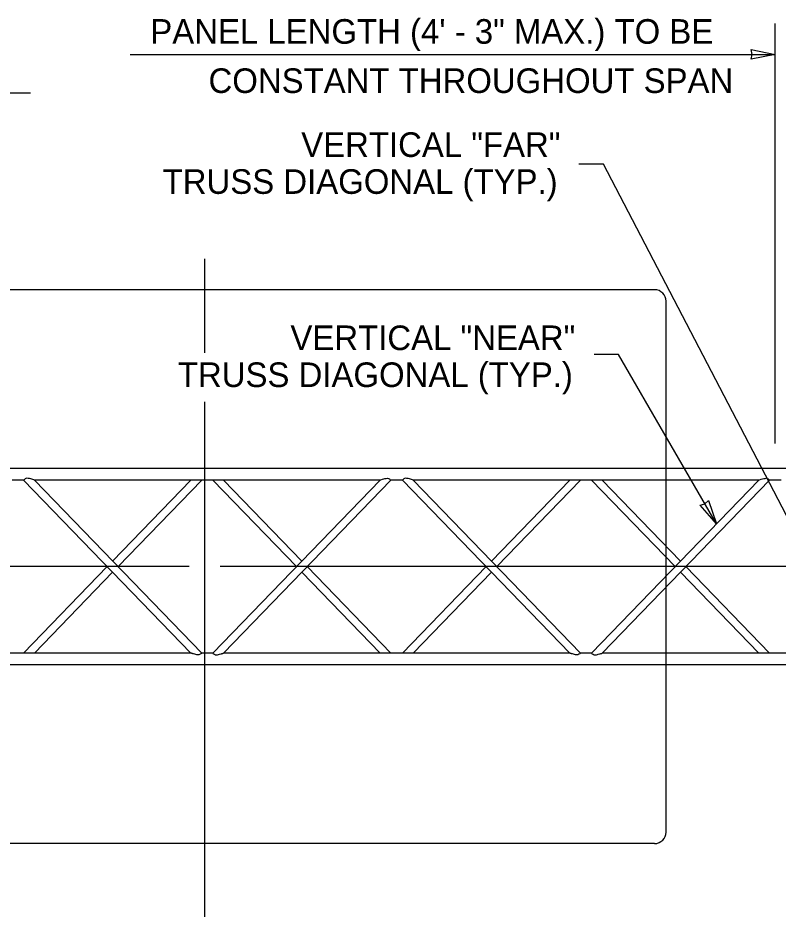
# Model space of a CAD drawing. Extents: x 99862 to 104211, y 98939 to 111076.
# Drawn here: x 101054 to 101548, y 101029 to 101608 of the extents above; entities that cross this region are included whole.
import ezdxf

# ---------------------------------------------------------------- set-up
doc = ezdxf.new("R2010")
doc.units = 0
for name, color, linetype in [('Level 15', 7, 'Continuous'), ('Level 20', 7, 'Continuous'), ('Level 6', 7, 'Continuous')]:
    doc.layers.add(name, color=color, linetype=linetype)

msp = doc.modelspace()

# ---------------------------------------------------------------- linework, layer by layer
at = {"layer": 'Level 15'}
for p, q in [((101546.37, 101331.16), (101546.37, 101604.16)), ((101126.95, 101584.16), (101546.37, 101584.16)), ((100920.81, 101559.16), (101062.26, 101559.16)), ((101434.65, 101512.85), (101418.65, 101512.85)), ((101582.66, 101228.49), (101434.65, 101512.85)), ((101175.37, 101451.16), (101175.37, 101390.1)), ((101444.54, 101389.08), (101428.54, 101389.08)), ((101508.13, 101278.95), (101444.55, 101389.08)), ((101175.37, 101358.32), (101175.37, 100843.55)), ((101165.37, 101251.16), (100695.37, 101251.16)), ((101773.38, 101251.16), (101185.37, 101251.16))]:
    msp.add_line(p, q, dxfattribs=at)
for points in [[(101546.37, 101584.16), (101530.64, 101581.08), (101531.37, 101584.16), (101530.64, 101587.25)], [(101508.13, 101278.95), (101497.6, 101291.02), (101500.63, 101291.93), (101502.94, 101294.11)]]:
    msp.add_lwpolyline(points, close=True, dxfattribs=at)
at = {"layer": 'Level 6'}
for p, q in [((101467.87, 101431.16), (100882.87, 101431.16)), ((101475.37, 101078.66), (101475.37, 101423.66)), ((101808.38, 101314.91), (100925.37, 101314.91)), ((101057.71, 101307.41), (101050.14, 101307.41)), ((101057.71, 101307.41), (101166.5, 101194.91)), ((101064.66, 101307.41), (101173.46, 101194.91)), ((101289.43, 101307.41), (101064.66, 101307.41)), ((101115.58, 101254.76), (101166.5, 101307.41)), ((101119.06, 101251.16), (101173.46, 101307.41)), ((101235.03, 101251.16), (101180.63, 101307.41)), ((101289.43, 101307.41), (101180.63, 101194.91)), ((101238.51, 101254.76), (101187.59, 101307.41)), ((101296.38, 101307.41), (101187.59, 101194.91)), ((101303.95, 101307.41), (101296.38, 101307.41)), ((101303.95, 101307.41), (101412.74, 101194.91)), ((101310.9, 101307.41), (101419.7, 101194.91)), ((101535.66, 101307.41), (101310.9, 101307.41)), ((101361.82, 101254.76), (101412.74, 101307.41)), ((101365.3, 101251.16), (101419.7, 101307.41)), ((101535.66, 101307.41), (101426.87, 101194.91)), ((101481.27, 101251.16), (101426.87, 101307.41)), ((101542.62, 101307.41), (101433.82, 101194.91)), ((101484.74, 101254.76), (101433.82, 101307.41)), ((101550.19, 101307.41), (101542.62, 101307.41)), ((101057.71, 101194.91), (101112.11, 101251.16)), ((101296.38, 101194.91), (101241.98, 101251.16)), ((101303.95, 101194.91), (101358.34, 101251.16)), ((101542.62, 101194.91), (101488.22, 101251.16)), ((101064.66, 101194.91), (101115.58, 101247.57)), ((101289.43, 101194.91), (101238.51, 101247.57)), ((101310.9, 101194.91), (101361.82, 101247.57)), ((101535.66, 101194.91), (101484.74, 101247.57)), ((101166.5, 101194.91), (100941.35, 101194.91)), ((101180.63, 101194.91), (101173.46, 101194.91)), ((101412.74, 101194.91), (101187.59, 101194.91)), ((101426.87, 101194.91), (101419.69, 101194.91)), ((101658.98, 101194.91), (101433.82, 101194.91)), ((101808.38, 101187.41), (100925.37, 101187.41)), ((101467.87, 101071.16), (100882.87, 101071.16))]:
    msp.add_line(p, q, dxfattribs=at)
for centre, start, end in [((101467.87, 101423.66), 0, 90), ((101467.87, 101078.66), 270, 0)]:
    msp.add_arc(centre, 7.5, start, end, dxfattribs=at)
for points, degree in [([(101064.66, 101307.41), (101064.65, 101307.42), (101063.43, 101307.8), (101059.5, 101309.06), (101057.59, 101307.36), (101057.73, 101307.42), (101057.71, 101307.41)], 3), ([(101057.71, 101307.41), (101057.7, 101307.41), (101057.7, 101307.42), (101057.7, 101307.42)], 2), ([(101173.46, 101307.41), (101173.46, 101307.41), (101173.46, 101307.41), (101173.46, 101307.41)], 2), ([(101173.46, 101307.41), (101173.46, 101307.41), (101173.46, 101307.41), (101173.47, 101307.41)], 2), ([(101180.63, 101307.41), (101180.63, 101307.41), (101180.63, 101307.41), (101180.62, 101307.41)], 2), ([(101180.63, 101307.41), (101180.63, 101307.41), (101180.63, 101307.41), (101180.63, 101307.41)], 2), ([(101289.43, 101307.41), (101289.44, 101307.42), (101290.66, 101307.8), (101294.59, 101309.06), (101296.5, 101307.36), (101296.36, 101307.42), (101296.38, 101307.41)], 3), ([(101296.38, 101307.41), (101296.39, 101307.41), (101296.39, 101307.42), (101296.39, 101307.42)], 2), ([(101310.9, 101307.41), (101310.89, 101307.42), (101309.67, 101307.8), (101305.74, 101309.06), (101303.83, 101307.36), (101303.97, 101307.42), (101303.95, 101307.41)], 3), ([(101303.95, 101307.41), (101303.94, 101307.41), (101303.94, 101307.42), (101303.94, 101307.42)], 2), ([(101419.69, 101307.41), (101419.7, 101307.41), (101419.7, 101307.41), (101419.7, 101307.41)], 2), ([(101419.7, 101307.41), (101419.7, 101307.41), (101419.7, 101307.41), (101419.7, 101307.41)], 2), ([(101426.87, 101307.41), (101426.87, 101307.41), (101426.86, 101307.41), (101426.86, 101307.41)], 2), ([(101426.87, 101307.41), (101426.87, 101307.41), (101426.87, 101307.41), (101426.87, 101307.41)], 2), ([(101535.66, 101307.41), (101535.68, 101307.42), (101536.9, 101307.8), (101540.83, 101309.06), (101542.74, 101307.36), (101542.59, 101307.42), (101542.62, 101307.41)], 3), ([(101542.62, 101307.41), (101542.63, 101307.41), (101542.63, 101307.42), (101542.63, 101307.42)], 2), ([(101173.46, 101194.91), (101173.59, 101194.93), (101171.67, 101193.4), (101168.76, 101194.27), (101167.57, 101194.57), (101167.26, 101194.67), (101167.02, 101194.75), (101166.82, 101194.81), (101166.66, 101194.86), (101166.55, 101194.9), (101166.51, 101194.91), (101166.5, 101194.91), (101166.5, 101194.91), (101166.5, 101194.91)], 3), ([(101166.5, 101194.91), (101166.5, 101194.91), (101166.5, 101194.91), (101166.51, 101194.91)], 2), ([(101173.46, 101194.91), (101173.46, 101194.92), (101173.46, 101194.92), (101173.46, 101194.91)], 2), ([(101180.63, 101194.91), (101180.5, 101194.93), (101182.42, 101193.4), (101185.33, 101194.27), (101186.52, 101194.57), (101186.82, 101194.67), (101187.07, 101194.75), (101187.27, 101194.81), (101187.43, 101194.86), (101187.53, 101194.9), (101187.58, 101194.91), (101187.59, 101194.91), (101187.59, 101194.91), (101187.59, 101194.91)], 3), ([(101180.63, 101194.91), (101180.63, 101194.92), (101180.63, 101194.92), (101180.63, 101194.91)], 2), ([(101187.59, 101194.91), (101187.59, 101194.91), (101187.58, 101194.91), (101187.58, 101194.91)], 2), ([(101419.7, 101194.91), (101419.83, 101194.93), (101417.91, 101193.4), (101415, 101194.27), (101413.81, 101194.57), (101413.5, 101194.67), (101413.26, 101194.75), (101413.06, 101194.81), (101412.9, 101194.86), (101412.79, 101194.9), (101412.75, 101194.91), (101412.74, 101194.91), (101412.74, 101194.91), (101412.74, 101194.91)], 3), ([(101412.74, 101194.91), (101412.74, 101194.91), (101412.74, 101194.91), (101412.74, 101194.91)], 2), ([(101419.69, 101194.91), (101419.7, 101194.92), (101419.7, 101194.92), (101419.7, 101194.91)], 2), ([(101426.87, 101194.91), (101426.74, 101194.93), (101428.66, 101193.4), (101431.57, 101194.27), (101432.76, 101194.57), (101433.06, 101194.67), (101433.31, 101194.75), (101433.51, 101194.81), (101433.67, 101194.86), (101433.77, 101194.9), (101433.81, 101194.91), (101433.82, 101194.91), (101433.82, 101194.91), (101433.82, 101194.91)], 3), ([(101426.87, 101194.91), (101426.87, 101194.92), (101426.87, 101194.92), (101426.87, 101194.91)], 2), ([(101433.82, 101194.91), (101433.82, 101194.91), (101433.82, 101194.91), (101433.82, 101194.91)], 2)]:
    msp.add_open_spline(points, degree=degree, dxfattribs=at)

# ---------------------------------------------------------------- texts
at = {"layer": 'Level 20'}
for s, p in [('PANEL LENGTH (4\' - 3" MAX.) TO BE ', (101140.07, 101591.04)), ('CONSTANT THROUGHOUT SPAN', (101177.9, 101559.04))]:
    msp.add_text(s, height=16, dxfattribs=at).set_placement(p)
for s, p in [('VERTICAL "FAR"', (101238.17, 101517.47)), ('TRUSS DIAGONAL (TYP.)', (101148.09, 101493.47)), ('VERTICAL "NEAR"', (101231.16, 101391.91)), ('TRUSS DIAGONAL (TYP.)', (101157.99, 101367.91))]:
    msp.add_text(s, height=16, rotation=360, dxfattribs=at).set_placement(p)

doc.saveas('drawing.dxf')
